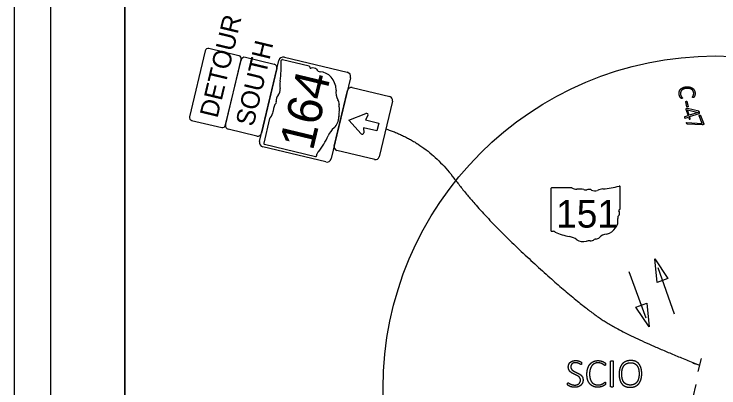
# Model space of a CAD drawing. Extents: x -740 to 1519, y 0 to 440.
# Drawn here: x 0 to 191, y 118.3 to 219.6 of the extents above; entities that cross this region are included whole.
import ezdxf

# ---------------------------------------------------------------- set-up
doc = ezdxf.new("R2010")
doc.units = 0
for name, color, linetype in [('Default', 7, 'Continuous'), ('GM_X_County_Road_Text', 7, 'Continuous'), ('GM_X_Major_Lake', 7, 'Continuous'), ('GM_X_Minor_River', 7, 'Continuous'), ('GM_X_Unincorporated_Location', 7, 'Continuous'), ('SH_Border', 7, 'Continuous'), ('SH_Cut_Line', 7, 'Continuous'), ('SH_Data', 7, 'Continuous')]:
    doc.layers.add(name, color=color, linetype=linetype)

msp = doc.modelspace()

# ---------------------------------------------------------------- linework, layer by layer
at = {"layer": 'Default'}
for p, q in [((174.47, 150.94), (178.91, 138.4)), ((171.28, 137.25), (166.69, 149.74))]:
    msp.add_line(p, q, dxfattribs=at)
for points in [[(174.25, 146.89), (173.64, 153.3), (177.19, 147.93)], [(171.45, 141.31), (172.15, 134.91), (168.53, 140.23)]]:
    msp.add_lwpolyline(points, close=True, dxfattribs=at)
at = {"layer": 'GM_X_County_Road_Text'}
for p, q in [((145.5, 172.35), (145.5, 160.96)), ((151.18, 172.54), (145.69, 172.54)), ((164.25, 166.87), (164.25, 172.82)), ((164.25, 166.87), (164.25, 166.87))]:
    msp.add_line(p, q, dxfattribs=at)
for centre, major_axis, start_param, end_param in [((145.72, 172.37), (0.217, 0), 1.712693, 3.28349), ((152.49, 173.86), (2.11, 0), 4.042523, 4.731795), ((153.18, 166.15), (7.56, 0), 1.404758, 1.657858), ((154.9, 172.43), (0.608, 0), 3.836095, 5.185415), ((155.79, 171.11), (1.26, 0), 0.950623, 2.079405), ((157.42, 172.92), (1.52, 0), 4.081561, 5.145723), ((160.11, 169.07), (4, 0), 1.699011, 2.107814), ((157.57, 188.06), (19.88, 0), 4.814394, 5.042369), ((164.04, 172.85), (0.209, 0), 6.141152, 7.989035), ((164.2, 166.43), (0.323, 0), 1.883978, 3.671073), ((162.15, 165.68), (1.94, 0), 5.934695, 6.695948), ((164.03, 166.85), (0.223, 0), 5.05454, 6.418171), ((165, 164.38), (1.41, 0), 2.387724, 3.262537), ((158.69, 163.62), (4.97, 0), 5.101752, 6.440018), ((145.72, 160.94), (0.219, 0), 3.00124, 4.508301), ((145.75, 162.1), (1.67, 0), 4.665946, 4.897461), ((146.09, 160.31), (0.603, 0), 0.519207, 1.627899), ((153.71, 170.53), (14.36, 0), 4.195997, 4.488961), ((149.43, 155.85), (4.49, 0), 0.823519, 1.323587), ((156.14, 159.4), (1.52, 0), 4.691044, 5.507374), ((157.52, 158.29), (0.428, 0), 1.147584, 2.315152), ((157.33, 159.86), (1.61, 0), 4.937069, 5.64225), ((160.78, 157.77), (2.72, 0), 1.647645, 2.488434), ((154.29, 160.25), (2.85, 0), 4.026481, 4.996735), ((155.93, 156.31), (2.34, 0), 1.495662, 1.94098)]:
    msp.add_ellipse(centre, major_axis=major_axis, ratio=0.8, start_param=start_param, end_param=end_param, dxfattribs=at)
at = {"layer": 'GM_X_Major_Lake'}
for p, q in [((161.67, 118.7), (161.67, 125.55)), ((162.34, 125.55), (162.34, 118.7)), ((154.19, 120.5), (154.19, 120.5)), ((169.38, 122.15), (169.38, 122.15)), ((170.1, 122.21), (170.1, 122.21)), ((160.31, 119.55), (160.31, 119.55))]:
    msp.add_line(p, q, dxfattribs=at)
for points in [[(150.2, 124), (150.2, 124.41), (150.34, 124.73)], [(150.34, 124.73), (150.49, 125.06), (150.76, 125.29)], [(150.76, 125.29), (151.03, 125.51), (151.4, 125.63)], [(150.96, 124.48), (150.88, 124.27), (150.88, 124.05)], [(151.19, 124.83), (151.04, 124.68), (150.96, 124.48)], [(151.59, 125.07), (151.35, 124.98), (151.19, 124.83)], [(151.4, 125.63), (151.78, 125.75), (152.22, 125.75)], [(152.15, 125.15), (151.83, 125.15), (151.59, 125.07)], [(152.74, 125.07), (152.48, 125.15), (152.15, 125.15)], [(152.22, 125.75), (152.45, 125.75), (152.68, 125.71)], [(152.68, 125.71), (152.91, 125.67), (153.11, 125.6)], [(153.18, 124.9), (153, 125), (152.74, 125.07)], [(153.11, 125.6), (153.32, 125.53), (153.48, 125.45)], [(153.49, 124.72), (153.37, 124.8), (153.18, 124.9)], [(153.48, 125.45), (153.64, 125.36), (153.69, 125.31)], [(153.67, 124.64), (153.61, 124.64), (153.49, 124.72)], [(153.73, 124.66), (153.71, 124.64), (153.67, 124.64)], [(153.69, 125.31), (153.74, 125.26), (153.76, 125.24)], [(153.77, 124.73), (153.76, 124.68), (153.73, 124.66)], [(153.76, 125.24), (153.77, 125.21), (153.78, 125.17)], [(153.8, 124.82), (153.79, 124.77), (153.77, 124.73)], [(153.78, 125.17), (153.79, 125.13), (153.8, 125.08)], [(153.8, 125.08), (153.8, 125.03), (153.8, 124.95)], [(153.8, 124.95), (153.8, 124.88), (153.8, 124.82)], [(155.46, 123.58), (155.68, 124.27), (156.07, 124.75)], [(156.07, 124.75), (156.47, 125.23), (157.02, 125.48)], [(156.59, 124.34), (156.29, 123.95), (156.12, 123.38)], [(157.3, 124.93), (156.89, 124.73), (156.59, 124.34)], [(157.02, 125.48), (157.58, 125.73), (158.25, 125.73)], [(158.21, 125.13), (157.72, 125.13), (157.3, 124.93)], [(159, 125.02), (158.67, 125.13), (158.21, 125.13)], [(158.25, 125.73), (158.56, 125.73), (158.86, 125.67)], [(158.86, 125.67), (159.16, 125.61), (159.41, 125.52)], [(159.55, 124.77), (159.32, 124.9), (159, 125.02)], [(159.41, 125.52), (159.66, 125.43), (159.86, 125.31)], [(159.92, 124.52), (159.78, 124.63), (159.55, 124.77)], [(159.86, 125.31), (160.06, 125.19), (160.13, 125.11)], [(160.13, 124.41), (160.06, 124.41), (159.92, 124.52)], [(160.13, 125.11), (160.21, 125.04), (160.23, 125.01)], [(160.2, 124.43), (160.17, 124.41), (160.13, 124.41)], [(160.24, 124.49), (160.23, 124.45), (160.2, 124.43)], [(160.23, 125.01), (160.25, 124.97), (160.26, 124.93)], [(160.27, 124.59), (160.26, 124.53), (160.24, 124.49)], [(160.26, 124.93), (160.27, 124.89), (160.27, 124.84)], [(160.27, 124.84), (160.28, 124.79), (160.28, 124.72)], [(160.28, 124.72), (160.28, 124.65), (160.27, 124.59)], [(161.67, 125.55), (161.67, 125.58), (161.69, 125.61)], [(161.69, 125.61), (161.71, 125.64), (161.75, 125.66)], [(161.75, 125.66), (161.79, 125.67), (161.86, 125.68)], [(161.86, 125.68), (161.92, 125.69), (162.01, 125.69)], [(162.01, 125.69), (162.11, 125.69), (162.17, 125.68)], [(162.17, 125.68), (162.23, 125.67), (162.27, 125.66)], [(162.27, 125.66), (162.31, 125.64), (162.32, 125.61)], [(162.32, 125.61), (162.34, 125.58), (162.34, 125.55)], [(164.75, 124.75), (164.36, 124.27), (164.17, 123.6)], [(165.73, 125.49), (165.14, 125.23), (164.75, 124.75)], [(164.81, 123.3), (164.93, 123.85), (165.21, 124.26)], [(165.21, 124.26), (165.5, 124.67), (165.95, 124.91)], [(167.11, 125.75), (166.31, 125.75), (165.73, 125.49)], [(165.95, 124.91), (166.4, 125.15), (167.05, 125.15)], [(167.05, 125.15), (167.71, 125.15), (168.16, 124.92)], [(168.44, 125.51), (167.88, 125.75), (167.11, 125.75)], [(168.16, 124.92), (168.61, 124.69), (168.88, 124.28)], [(169.37, 124.8), (169, 125.26), (168.44, 125.51)], [(168.88, 124.28), (169.15, 123.88), (169.27, 123.33)], [(169.92, 123.69), (169.74, 124.34), (169.37, 124.8)], [(150.34, 123.27), (150.2, 123.58), (150.2, 124)], [(150.71, 122.74), (150.48, 122.97), (150.34, 123.27)], [(151.24, 122.34), (150.94, 122.51), (150.71, 122.74)], [(150.88, 124.05), (150.88, 123.72), (151.02, 123.49)], [(151.02, 123.49), (151.16, 123.25), (151.4, 123.07)], [(151.84, 122.03), (151.53, 122.18), (151.24, 122.34)], [(151.4, 123.07), (151.63, 122.89), (151.93, 122.75)], [(151.93, 122.75), (152.23, 122.6), (152.53, 122.46)], [(152.53, 122.46), (152.84, 122.31), (153.14, 122.15)], [(155.24, 122.03), (155.24, 122.9), (155.46, 123.58)], [(156.12, 123.38), (155.96, 122.82), (155.96, 122.08)], [(164.17, 123.6), (163.97, 122.92), (163.97, 122.09)], [(164.69, 122.15), (164.69, 122.76), (164.81, 123.3)], [(169.27, 123.33), (169.38, 122.78), (169.38, 122.15)], [(170.1, 122.21), (170.1, 123.03), (169.92, 123.69)], [(152.45, 121.74), (152.15, 121.89), (151.84, 122.03)], [(152.97, 121.42), (152.74, 121.6), (152.45, 121.74)], [(153.35, 121.01), (153.21, 121.24), (152.97, 121.42)], [(153.14, 122.15), (153.44, 121.98), (153.67, 121.75)], [(153.49, 120.44), (153.49, 120.77), (153.35, 121.01)], [(153.38, 119.88), (153.49, 120.13), (153.49, 120.44)], [(153.67, 121.75), (153.91, 121.53), (154.05, 121.22)], [(154.19, 120.5), (154.19, 120.03), (154.02, 119.66)], [(154.05, 121.22), (154.19, 120.92), (154.19, 120.5)], [(155.44, 120.54), (155.24, 121.19), (155.24, 122.03)], [(156.03, 119.43), (155.65, 119.88), (155.44, 120.54)], [(155.96, 122.08), (155.96, 121.37), (156.11, 120.83)], [(156.11, 120.83), (156.26, 120.28), (156.55, 119.91)], [(163.97, 122.09), (163.97, 121.25), (164.15, 120.59)], [(164.15, 120.59), (164.32, 119.92), (164.68, 119.46)], [(164.8, 120.95), (164.69, 121.5), (164.69, 122.15)], [(165.18, 119.99), (164.91, 120.4), (164.8, 120.95)], [(169.26, 120.99), (169.14, 120.44), (168.86, 120.03)], [(169.38, 122.15), (169.38, 121.54), (169.26, 120.99)], [(169.32, 119.51), (169.71, 119.99), (169.9, 120.68)], [(169.9, 120.68), (170.1, 121.36), (170.1, 122.21)], [(150, 119.4), (150, 119.49), (150.01, 119.55)], [(150.02, 119.19), (150, 119.27), (150, 119.4)], [(150.01, 119.55), (150.02, 119.61), (150.04, 119.65)], [(150.11, 119.04), (150.05, 119.1), (150.02, 119.19)], [(150.04, 119.65), (150.06, 119.69), (150.09, 119.7)], [(150.09, 119.7), (150.12, 119.72), (150.15, 119.72)], [(150.33, 118.89), (150.17, 118.98), (150.11, 119.04)], [(150.15, 119.72), (150.23, 119.72), (150.36, 119.62)], [(150.73, 118.71), (150.49, 118.8), (150.33, 118.89)], [(150.36, 119.62), (150.5, 119.53), (150.73, 119.42)], [(150.73, 119.42), (150.95, 119.3), (151.25, 119.21)], [(151.26, 118.56), (150.96, 118.62), (150.73, 118.71)], [(151.25, 119.21), (151.56, 119.11), (151.97, 119.11)], [(151.9, 118.5), (151.56, 118.5), (151.26, 118.56)], [(152.82, 118.63), (152.4, 118.5), (151.9, 118.5)], [(151.97, 119.11), (152.31, 119.11), (152.58, 119.2)], [(152.58, 119.2), (152.86, 119.29), (153.06, 119.46)], [(153.55, 119.03), (153.24, 118.77), (152.82, 118.63)], [(153.06, 119.46), (153.27, 119.63), (153.38, 119.88)], [(154.02, 119.66), (153.85, 119.29), (153.55, 119.03)], [(156.95, 118.75), (156.41, 118.98), (156.03, 119.43)], [(156.55, 119.91), (156.84, 119.53), (157.27, 119.34)], [(158.16, 118.52), (157.49, 118.52), (156.95, 118.75)], [(157.27, 119.34), (157.7, 119.14), (158.24, 119.14)], [(158.91, 118.6), (158.57, 118.52), (158.16, 118.52)], [(158.24, 119.14), (158.68, 119.14), (159.01, 119.25)], [(159.52, 118.8), (159.26, 118.68), (158.91, 118.6)], [(159.01, 119.25), (159.34, 119.36), (159.58, 119.5)], [(159.96, 119.03), (159.79, 118.91), (159.52, 118.8)], [(159.58, 119.5), (159.81, 119.63), (159.96, 119.75)], [(159.96, 119.75), (160.11, 119.86), (160.19, 119.86)], [(160.19, 119.2), (160.14, 119.15), (159.96, 119.03)], [(160.19, 119.86), (160.23, 119.86), (160.25, 119.84)], [(160.26, 119.28), (160.24, 119.25), (160.19, 119.2)], [(160.25, 119.84), (160.27, 119.83), (160.28, 119.8)], [(160.29, 119.36), (160.28, 119.32), (160.26, 119.28)], [(160.28, 119.8), (160.3, 119.76), (160.3, 119.7)], [(160.31, 119.44), (160.3, 119.39), (160.29, 119.36)], [(160.3, 119.7), (160.31, 119.64), (160.31, 119.55)], [(160.31, 119.55), (160.31, 119.49), (160.31, 119.44)], [(161.69, 118.64), (161.67, 118.67), (161.67, 118.7)], [(161.74, 118.6), (161.71, 118.61), (161.69, 118.64)], [(161.85, 118.57), (161.78, 118.58), (161.74, 118.6)], [(162.01, 118.56), (161.91, 118.56), (161.85, 118.57)], [(162.17, 118.57), (162.11, 118.56), (162.01, 118.56)], [(162.27, 118.6), (162.23, 118.58), (162.17, 118.57)], [(162.32, 118.64), (162.31, 118.61), (162.27, 118.6)], [(162.34, 118.7), (162.34, 118.67), (162.32, 118.64)], [(164.68, 119.46), (165.05, 119), (165.61, 118.75)], [(165.89, 119.34), (165.45, 119.58), (165.18, 119.99)], [(165.61, 118.75), (166.18, 118.5), (166.96, 118.5)], [(167.01, 119.11), (166.34, 119.11), (165.89, 119.34)], [(166.96, 118.5), (167.75, 118.5), (168.34, 118.76)], [(168.13, 119.36), (167.68, 119.11), (167.01, 119.11)], [(168.86, 120.03), (168.59, 119.61), (168.13, 119.36)], [(168.34, 118.76), (168.93, 119.02), (169.32, 119.51)]]:
    msp.add_open_spline(points, degree=2, dxfattribs=at)
at = {"layer": 'GM_X_Minor_River'}
for p, q in [((57.3, 189.64), (61.5, 207.15)), ((62.7, 207.89), (70.48, 206.02)), ((79.95, 205.52), (72.71, 207.25)), ((71.22, 204.82), (67.03, 187.31)), ((79.94, 205.52), (79.95, 205.52)), ((86.77, 183.86), (90.38, 198.94)), ((91.59, 199.68), (101.8, 197.23)), ((102.54, 196.02), (98.92, 180.95)), ((69.24, 191.28), (67.64, 184.61)), ((90.7, 190.89), (95.32, 192.66)), ((95.9, 192.09), (95.21, 190.93)), ((94.06, 187.16), (90.7, 190.89)), ((95.21, 190.93), (98.86, 190.06)), ((98.86, 190.06), (98.35, 187.93)), ((65.82, 186.57), (58.04, 188.44)), ((98.35, 187.93), (94.7, 188.81)), ((94.7, 188.81), (94.79, 187.47)), ((67.83, 184.32), (81.66, 181.01)), ((97.72, 180.21), (87.51, 182.66)), ((186.16, 126.26), (185.32, 122.75)), ((185.74, 124.5), (183.99, 124.92)), ((184.03, 115.8), (184.87, 119.3))]:
    msp.add_line(p, q, dxfattribs=at)
for points in [[(60.95, 208.31), (52.79, 210.26)], [(51.82, 209.67), (47.53, 191.78)], [(57.26, 189.45), (61.55, 207.34)], [(66.5, 185.12), (71.75, 207)], [(73.26, 207.93), (90.27, 203.85)], [(91.2, 202.34), (85.95, 180.46)], [(48.12, 190.81), (56.29, 188.86)], [(84.45, 179.54), (67.43, 183.62)]]:
    msp.add_lwpolyline(points, dxfattribs=at)
for centre, radius, start, end in [((52.6, 209.49), 0.8, 76.5198, 166.5198), ((60.77, 207.53), 0.8, 346.5198, 76.5198), ((62.47, 206.91), 1, 76.5198, 166.5198), ((72.96, 206.71), 1.25, 76.5198, 166.5198), ((70.25, 205.05), 1, 346.5198, 76.5198), ((89.98, 202.63), 1.25, 346.5198, 76.5198), ((91.35, 198.7), 1, 76.5198, 166.5198), ((101.56, 196.26), 1, 346.5198, 76.5198), ((48.31, 191.59), 0.8, 166.5198, 256.5198), ((95.54, 192.3), 0.417, 329.3152, 121.5294), ((56.48, 189.63), 0.8, 256.5198, 346.5198), ((58.28, 189.41), 1, 166.5198, 256.5198), ((66.06, 187.54), 1, 256.5198, 346.5198), ((94.37, 187.44), 0.417, 221.9311, 3.7244), ((67.72, 184.83), 1.25, 166.5198, 256.5198), ((87.74, 183.63), 1, 166.5198, 256.5198), ((84.74, 180.75), 1.25, 256.5198, 346.5198), ((97.95, 181.18), 1, 256.5198, 346.5198)]:
    msp.add_arc(centre, radius, start, end, dxfattribs=at)
for centre, major_axis, start_param, end_param in [((52.24, 203.58), (5.79, 24.17), 4.814394, 5.042369), ((72.62, 207.01), (0.061, 0.254), 6.141152, 7.989035), ((79.91, 205.24), (0.065, 0.272), 5.05454, 6.418171), ((80.46, 205.33), (0.094, 0.393), 1.883978, 3.671073), ((80.78, 202.62), (0.57, 2.36), 5.934695, 6.695948), ((83.19, 205.7), (0.41, 1.71), 2.387724, 3.262537), ((82.28, 197.81), (1.45, 6.05), 5.101752, 6.440018), ((76.07, 201.12), (1.17, 4.86), 1.699011, 2.107814), ((70.6, 198.98), (0.44, 1.85), 4.081561, 5.145723), ((90, 198.65), (0.79, 3.31), 1.647645, 2.488434), ((72.32, 196.47), (0.37, 1.54), 0.950623, 2.079405), ((77.59, 191.86), (2.2, 9.19), 1.404758, 1.657858), ((70.46, 195.77), (0.177, 0.739), 3.836095, 5.185415), ((86.45, 195.07), (0.47, 1.95), 4.937069, 5.64225), ((88.41, 194.83), (0.125, 0.52), 1.147584, 2.315152), ((90.35, 192.33), (0.68, 2.85), 1.495662, 1.94098), ((86.67, 193.48), (0.44, 1.85), 4.691044, 5.507374), ((68.02, 193.25), (0.61, 2.56), 4.042523, 4.731795), ((85.09, 191.48), (0.83, 3.47), 4.026481, 4.996735), ((89.02, 184.29), (1.31, 5.46), 0.823519, 1.323587), ((72.42, 193.77), (4.18, 17.45), 4.195997, 4.488961), ((67.86, 184.59), (0.063, 0.264), 1.712693, 3.28349), ((80.35, 181.64), (0.49, 2.03), 4.665946, 4.897461), ((82.63, 181.54), (0.176, 0.733), 0.519207, 1.627899), ((81.76, 181.26), (0.064, 0.266), 3.00124, 4.508301)]:
    msp.add_ellipse(centre, major_axis=major_axis, ratio=0.8, start_param=start_param, end_param=end_param, dxfattribs=at)
at = {"layer": 'GM_X_Unincorporated_Location'}
for p, q in [((180.93, 196.75), (180.93, 196.75)), ((182.35, 194.51), (182.02, 195.85)), ((182.34, 195.92), (182.67, 194.59)), ((185.55, 193.29), (182.46, 194)), ((182.53, 194.46), (182.53, 194.46)), ((183.13, 191.14), (183.13, 191.14)), ((186.03, 192.15), (186.89, 189.86)), ((186.49, 189.62), (182.48, 189.82)), ((186.77, 189.66), (186.77, 189.66))]:
    msp.add_line(p, q, dxfattribs=at)
for points in [[(182.07, 193.82), (182.64, 192.08), (181.73, 191.78)], [(181.85, 191.41), (182.76, 191.71), (182.93, 191.2)], [(182.36, 190.22), (186.46, 189.99), (185.69, 192.02)], [(183.25, 191.3), (183.08, 191.82), (185.74, 192.69)]]:
    msp.add_lwpolyline(points, dxfattribs=at)
msp.add_lwpolyline([(185.37, 192.98), (182.96, 192.19), (182.49, 193.64), (185.37, 192.98)], close=True, dxfattribs=at)
for points in [[(180.22, 198), (180.2, 198.4), (180.31, 198.74)], [(180.31, 198.74), (180.43, 199.07), (180.68, 199.31)], [(180.68, 199.31), (180.93, 199.56), (181.32, 199.71)], [(180.99, 199.02), (180.78, 198.83), (180.68, 198.57)], [(181.52, 199.32), (181.2, 199.21), (180.99, 199.02)], [(181.32, 199.71), (181.7, 199.86), (182.21, 199.89)], [(182.26, 199.47), (181.84, 199.44), (181.52, 199.32)], [(182.21, 199.89), (182.72, 199.93), (183.14, 199.83)], [(183.05, 199.42), (182.7, 199.5), (182.26, 199.47)], [(183.64, 199.18), (183.4, 199.34), (183.05, 199.42)], [(183.14, 199.83), (183.56, 199.73), (183.87, 199.51)], [(184.02, 198.78), (183.89, 199.02), (183.64, 199.18)], [(183.87, 199.51), (184.17, 199.29), (184.34, 198.97)], [(184.18, 198.24), (184.16, 198.54), (184.02, 198.78)], [(184.34, 198.97), (184.52, 198.65), (184.55, 198.25)], [(180.3, 197.55), (180.24, 197.75), (180.22, 198)], [(180.45, 197.2), (180.37, 197.35), (180.3, 197.55)], [(180.6, 196.94), (180.53, 197.04), (180.45, 197.2)], [(180.68, 198.57), (180.58, 198.3), (180.6, 197.98)], [(180.6, 197.98), (180.62, 197.71), (180.7, 197.52)], [(180.72, 196.81), (180.68, 196.84), (180.6, 196.94)], [(180.7, 197.52), (180.78, 197.33), (180.87, 197.19)], [(180.77, 196.77), (180.75, 196.78), (180.72, 196.81)], [(180.81, 196.76), (180.79, 196.76), (180.77, 196.77)], [(180.87, 196.75), (180.84, 196.75), (180.81, 196.76)], [(180.87, 197.19), (180.96, 197.06), (181.03, 196.97)], [(180.93, 196.75), (180.9, 196.75), (180.87, 196.75)], [(181.02, 196.77), (180.98, 196.76), (180.93, 196.75)], [(181.08, 196.78), (181.06, 196.77), (181.02, 196.77)], [(181.03, 196.97), (181.11, 196.89), (181.11, 196.84)], [(181.1, 196.81), (181.1, 196.79), (181.08, 196.78)], [(181.11, 196.84), (181.11, 196.82), (181.1, 196.81)], [(183.83, 197.06), (183.83, 197.11), (183.89, 197.2)], [(183.85, 197.03), (183.83, 197.04), (183.83, 197.06)], [(183.89, 197), (183.86, 197.01), (183.85, 197.03)], [(183.89, 197.2), (183.95, 197.29), (184.02, 197.43)], [(183.95, 196.99), (183.91, 196.99), (183.89, 197)], [(184.03, 196.99), (183.98, 196.99), (183.95, 196.99)], [(184.02, 197.43), (184.09, 197.57), (184.15, 197.77)], [(184.1, 197), (184.07, 196.99), (184.03, 196.99)], [(184.15, 197.01), (184.13, 197), (184.1, 197)], [(184.15, 197.77), (184.2, 197.97), (184.18, 198.24)], [(184.19, 197.03), (184.17, 197.02), (184.15, 197.01)], [(184.25, 197.09), (184.21, 197.04), (184.19, 197.03)], [(184.36, 197.26), (184.29, 197.14), (184.25, 197.09)], [(184.47, 197.54), (184.42, 197.39), (184.36, 197.26)], [(184.54, 197.88), (184.51, 197.7), (184.47, 197.54)], [(184.55, 198.25), (184.56, 198.06), (184.54, 197.88)], [(182.02, 195.85), (182.01, 195.89), (182.04, 195.92)], [(182.04, 195.92), (182.07, 195.96), (182.16, 195.98)], [(182.16, 195.98), (182.25, 196), (182.29, 195.98)], [(182.29, 195.98), (182.33, 195.97), (182.34, 195.92)], [(182.08, 193.92), (182.06, 193.89), (182.06, 193.87)], [(182.06, 193.87), (182.06, 193.84), (182.07, 193.82)], [(182.12, 193.96), (182.09, 193.94), (182.08, 193.92)], [(182.19, 193.99), (182.15, 193.98), (182.12, 193.96)], [(182.27, 194.01), (182.23, 194), (182.19, 193.99)], [(182.33, 194.02), (182.3, 194.02), (182.27, 194.01)], [(182.39, 194.02), (182.36, 194.02), (182.33, 194.02)], [(182.4, 194.45), (182.36, 194.47), (182.35, 194.51)], [(182.46, 194), (182.42, 194.01), (182.39, 194.02)], [(182.53, 194.46), (182.44, 194.43), (182.4, 194.45)], [(182.61, 194.48), (182.58, 194.47), (182.53, 194.46)], [(182.65, 194.51), (182.64, 194.5), (182.61, 194.48)], [(182.67, 194.55), (182.67, 194.53), (182.65, 194.51)], [(182.67, 194.59), (182.68, 194.57), (182.67, 194.55)], [(185.61, 193.26), (185.58, 193.28), (185.55, 193.29)], [(185.65, 193.21), (185.63, 193.24), (185.61, 193.26)], [(185.7, 193.13), (185.68, 193.18), (185.65, 193.21)], [(185.74, 193.02), (185.72, 193.08), (185.7, 193.13)], [(185.78, 192.89), (185.76, 192.94), (185.74, 193.02)], [(181.7, 191.76), (181.68, 191.75), (181.68, 191.73)], [(181.68, 191.73), (181.68, 191.7), (181.68, 191.66)], [(181.68, 191.66), (181.69, 191.63), (181.71, 191.57)], [(181.73, 191.78), (181.71, 191.78), (181.7, 191.76)], [(181.71, 191.57), (181.73, 191.52), (181.74, 191.48)], [(181.74, 191.48), (181.76, 191.45), (181.78, 191.43)], [(181.78, 191.43), (181.79, 191.41), (181.81, 191.41)], [(181.81, 191.41), (181.83, 191.4), (181.85, 191.41)], [(182.93, 191.2), (182.95, 191.14), (183, 191.13)], [(183, 191.13), (183.06, 191.11), (183.13, 191.14)], [(183.13, 191.14), (183.21, 191.16), (183.24, 191.21)], [(183.24, 191.21), (183.27, 191.25), (183.25, 191.3)], [(185.69, 192.02), (185.67, 192.08), (185.71, 192.13)], [(185.71, 192.13), (185.75, 192.17), (185.82, 192.2)], [(185.74, 192.69), (185.77, 192.69), (185.78, 192.72)], [(185.79, 192.79), (185.79, 192.83), (185.78, 192.89)], [(185.78, 192.72), (185.79, 192.75), (185.79, 192.79)], [(185.82, 192.2), (185.86, 192.22), (185.89, 192.22)], [(185.89, 192.22), (185.92, 192.22), (185.95, 192.22)], [(185.95, 192.22), (185.98, 192.21), (186, 192.19)], [(186, 192.19), (186.02, 192.18), (186.03, 192.15)], [(182.24, 190.13), (182.24, 190.17), (182.25, 190.19)], [(182.27, 190.02), (182.25, 190.09), (182.24, 190.13)], [(182.25, 190.19), (182.26, 190.22), (182.29, 190.22)], [(182.32, 189.92), (182.3, 189.96), (182.27, 190.02)], [(182.29, 190.22), (182.32, 190.23), (182.36, 190.22)], [(182.36, 189.86), (182.34, 189.88), (182.32, 189.92)], [(182.41, 189.83), (182.38, 189.84), (182.36, 189.86)], [(182.48, 189.82), (182.44, 189.82), (182.41, 189.83)], [(186.57, 189.62), (186.53, 189.61), (186.49, 189.62)], [(186.64, 189.62), (186.6, 189.62), (186.57, 189.62)], [(186.7, 189.64), (186.67, 189.63), (186.64, 189.62)], [(186.77, 189.66), (186.74, 189.65), (186.7, 189.64)], [(186.85, 189.7), (186.82, 189.68), (186.77, 189.66)], [(186.89, 189.74), (186.87, 189.72), (186.85, 189.7)], [(186.89, 189.86), (186.9, 189.83), (186.9, 189.79)], [(186.9, 189.79), (186.9, 189.76), (186.89, 189.74)]]:
    msp.add_open_spline(points, degree=2, dxfattribs=at)
at = {"layer": 'SH_Border'}
for points in [[(10, 430), (30, 430), (30, 10), (10, 10)], [(30, 430), (670, 430), (670, 10), (30, 10)]]:
    msp.add_lwpolyline(points, close=True, dxfattribs=at)
at = {"layer": 'SH_Cut_Line'}
msp.add_lwpolyline([(0, 0), (680, 0), (680, 440), (0, 440)], close=True, dxfattribs=at)
at = {"layer": 'SH_Data'}
msp.add_circle((190, 118.25), 90, dxfattribs=at)
msp.add_open_spline([(100.73, 188.49), (111.81, 184.99), (126.7, 165.18), (152.91, 141.04), (166.48, 132.17), (185.74, 124.5)], degree=2, dxfattribs=at)

# ---------------------------------------------------------------- texts
at = {"layer": 'GM_X_County_Road_Text'}
msp.add_text('151', height=7.5, dxfattribs=at).set_placement((146.91, 161.76))
at = {"layer": 'GM_X_Minor_River'}
for s, height, p in [('DETOUR', 5, (55.11, 191.23)), ('SOUTH', 5, (64.85, 188.95)), ('164', 9.375, (80.96, 182.36))]:
    msp.add_text(s, height=height, rotation=76.5198, dxfattribs=at).set_placement(p)

doc.saveas('drawing.dxf')
